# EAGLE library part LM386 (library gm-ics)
LM386 - Low Voltage Audio Power Amplifier
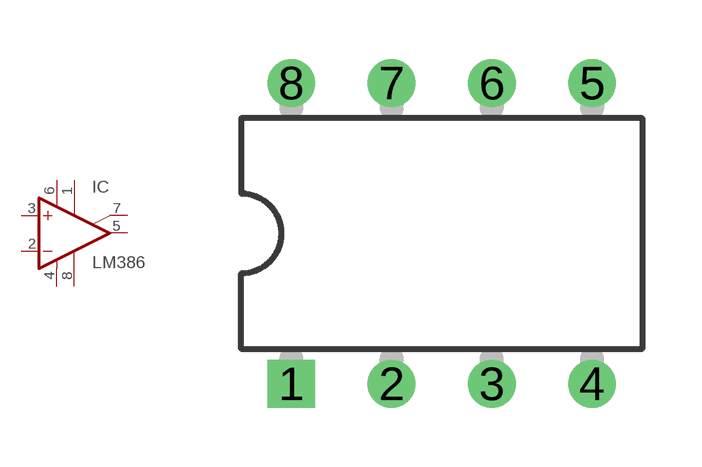
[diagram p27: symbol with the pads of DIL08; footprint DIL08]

Designator prefix IC

## LM386  [DIL08]
1  GAIN1  pas
2  -IN  in
3  +IN  in
4  V-  pwr
5  OUT  out
6  V+  pwr
7  BYPASS  pas
8  GAIN2  pas

## Footprint DIL08 (pad centres in mm)
Dual In Line Package
drill 0.7 square: 1 -3.81,-3.81
drill 0.7 round: 2 -1.27,-3.81; 3 1.27,-3.81; 4 3.81,-3.81; 5 3.81,3.81; 6 1.27,3.81; 7 -1.27,3.81; 8 -3.81,3.81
